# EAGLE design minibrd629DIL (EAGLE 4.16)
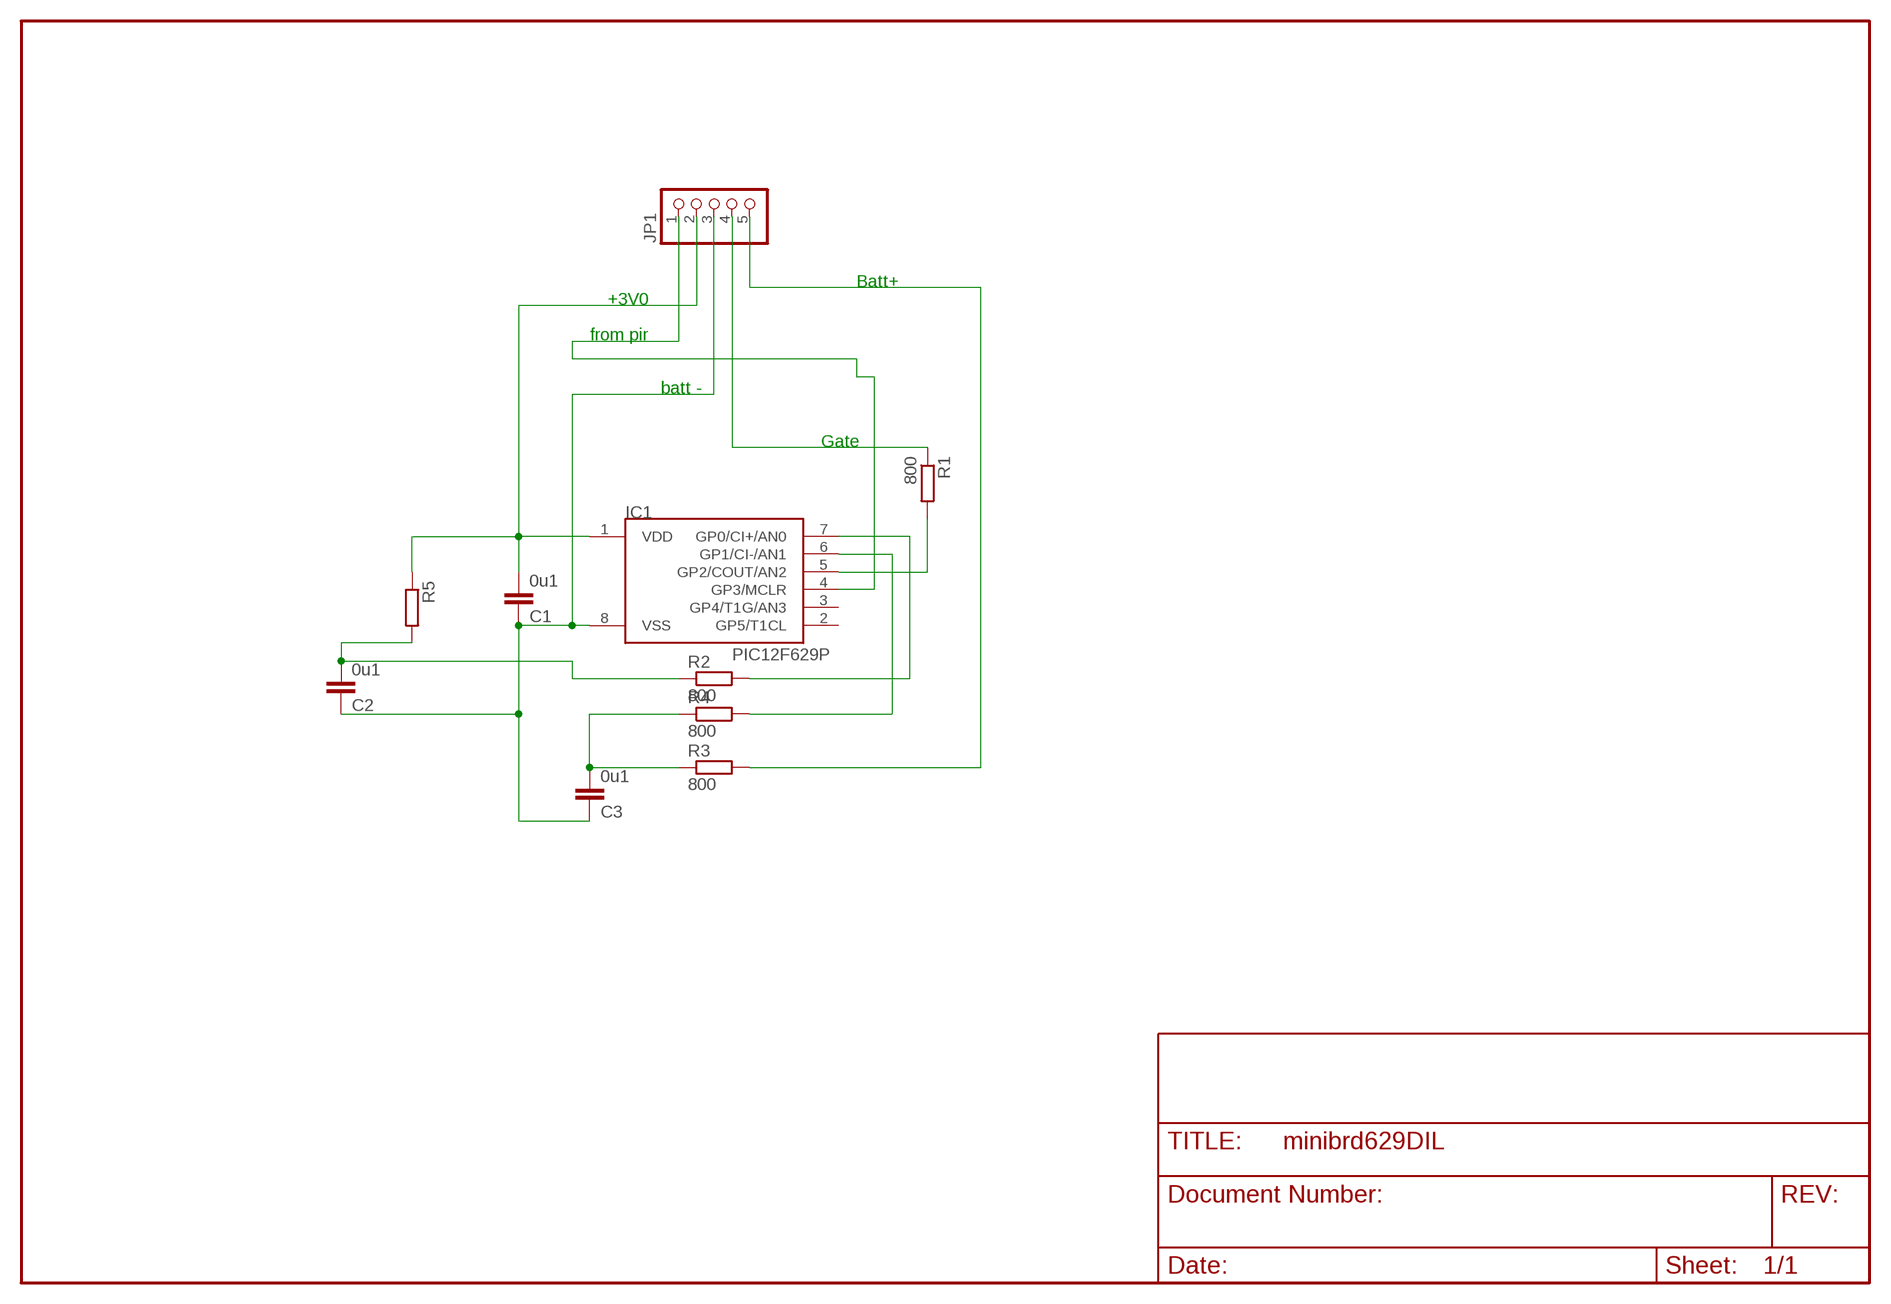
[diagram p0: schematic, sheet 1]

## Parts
C1  0u1  C-EUC1206  [C1206]
C2  0u1  C-EUC1206  [C1206]
C3  0u1  C-EUC1206  [C1206]
IC1  PIC12F629P  [DIL8]
JP1  PINHD-1X5  [1X05]
R1  800  R-EU_R1206  [R1206]
R2  800  R-EU_R1206  [R1206]
R3  800  R-EU_R1206  [R1206]
R4  800  R-EU_R1206  [R1206]
R5  R-EU_0613/5V  [P0613V]

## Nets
GATE: JP1.4 R1.1
N$1: IC1.5(GP2/COUT/AN2) R1.2
N$4: IC1.7(GP0/CI+/AN0) R2.2
N$7: C3.2 R3.1 R4.1
N$8: IC1.6(GP1/CI-/AN1) R4.2
N$9: C2.2 R2.1 R5.2
PIR: IC1.4(GP3/MCLR) JP1.1
V3: C1.2 IC1.1(VDD) JP1.2 R5.1
V+: JP1.5 R3.2
V-: C1.1 C2.1 C3.1 IC1.8(VSS) JP1.3
Unconnected: IC1.2(GP5/T1CL) IC1.3(GP4/T1G/AN3)

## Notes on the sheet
- Batt+
- +3V0
- from pir
- batt -
- Gate

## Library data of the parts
C1-C3 = rcl:C-EU: CAPACITOR, European symbol
IC1 = microchip-3:PIC12F6*: uPC nW 1k Program Flash memory 2x Timer Comparator 10b A/D converter/ 4xIN
JP1 = pinhead:PINHD-1X5: PIN HEADER
R1-R5 = rcl:R-EU_: RESISTOR, European symbol

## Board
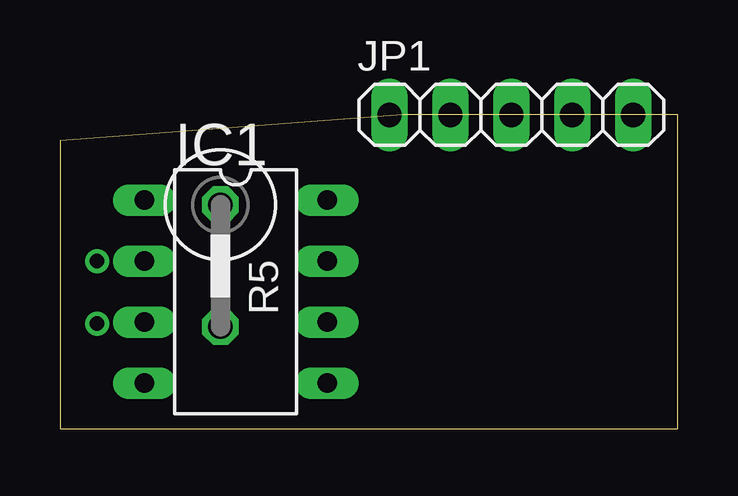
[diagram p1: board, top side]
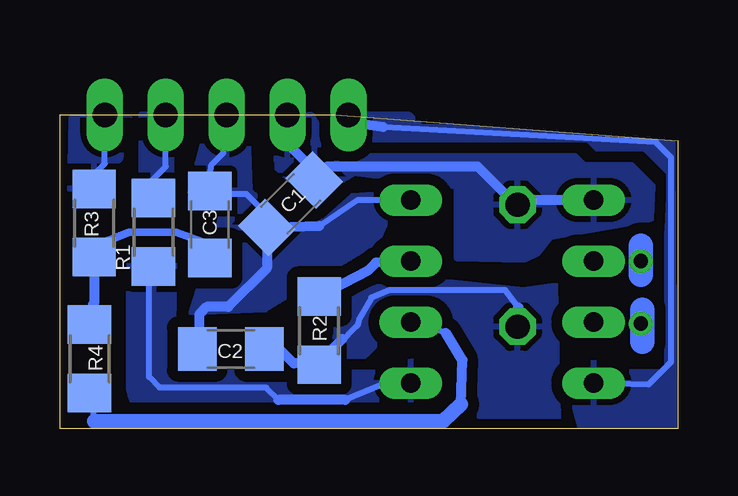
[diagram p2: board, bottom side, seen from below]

Size 25.77 x 13.08 mm. Coordinates in mm from the lower left corner, seen from the top.
Outline: 0,0 25.77,0 25.77,13.07 18,13.07 14.31,13.08 0,11.99 0,0
Copper layers (1*16): Top 0.035mm / dielectric 1.5mm / Bottom 0.035mm
Design rules "default": minimum track width 10mil, minimum drill 24mil, track to track 18mil, track to pad 18mil, pad to pad 8mil, via to via 8mil, smd to smd 8mil, copper to edge 1mil, drill to drill 8mil, minimum pad ring 10mil, minimum via ring 8mil, stop-mask expansion 4mil, vias tented up to drill 0mil, thermal gap 10mil

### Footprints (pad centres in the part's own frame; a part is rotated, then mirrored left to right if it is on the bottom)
C1206 = smd 1.6 x 1.8: 1 -1.4,0; 2 1.4,0
DIL8 = drill 0.813 long: 1 -3.81,-3.81; 2 -1.27,-3.81; 3 1.27,-3.81; 4 3.81,-3.81; 5 3.81,3.81; 6 1.27,3.81; 7 -1.27,3.81; 8 -3.81,3.81
1X05 = drill 1.016 long: 1 -5.08,0; 2 -2.54,0; 3 0,0; 4 2.54,0; 5 5.08,0
R1206 = smd 1.6 x 1.803: 1 -1.422,0; 2 1.422,0
P0613V = drill 1.016 octagon: 1 -2.54,0; 2 2.54,0

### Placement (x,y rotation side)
C1  16.15,9.37 45 bottom
C2  18.64,3.32 0 bottom
C3  19.52,8.5 270 bottom
IC1  7.33,5.71 270 top
JP1  18.82,13.08 0 top
R1  21.87,8.19 270 bottom
R2  14.96,4.09 90 bottom
R3  24.35,8.57 90 bottom
R4  24.54,2.92 270 bottom
R5  6.69,6.79 270 top

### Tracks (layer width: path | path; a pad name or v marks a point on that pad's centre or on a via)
GATE
  Bottom 0.254: JP1.4 21.36,10.92 22.06,10.22 22.06,9.52 21.97,9.61 R1.1
  pour Bottom: 21.11,13.14 22.31,13.14 22.38,13.08 22.38,10.66 22.5,10.54 21.23,10.54 21.11,10.66 21.11,13.01
N$1
  Bottom 0.254: IC1.5 12.34,1.84 13.87,1.2 | R1.2 21.55,6.79 22.06,6.28 22.06,2.15 21.62,1.71 17.17,1.71 16.66,1.2
  Bottom 0.406: 13.87,1.2 16.66,1.2
  pour Bottom (isolate 0.406): 11.46,2.79 10.57,2.85 9.99,2.79 9.99,1.2 22.76,1.2 22.89,1.65 22.89,7.42 22.76,7.55 21.04,7.55 20.98,7.49 21.04,4.38 20.47,3.11 19.71,2.34 12.66,2.34 12.47,2.54 11.71,2.54
N$2  (via drill 0.6)
  other vias: 1.55,4.38
N$3  (via drill 0.6)
  other vias: 1.55,6.98
N$4
  Bottom 0.406: R2.2 12.93,6.59 12.6,6.92 IC1.7
N$5
  Bottom 1.016: 1.49,3.61 1.49,4.95
N$6
  Bottom 1.016: 1.55,6.41 1.55,7.62
N$7
  Bottom 0.254: C3.2 19.39,7.62 | 24.47,7.55 24.45,7.53 R3.1 | R4.1 24.47,5.2 24.41,5.14 24.35,5.2
  Bottom 0.305: 19.39,7.62 20.92,8.19 22.89,8.19 24.47,7.55
  Bottom 0.406: R3.1 24.35,5.2
N$8
  Bottom 0.254: R4.2 24.47,2.15 24.35,0.31 | 9.68,4 IC1.6
  Bottom 0.406: 9.04,1.01 8.98,2.85 9.68,4
  Bottom 0.61: 24.35,0.31 9.8,0.31 9.04,1.01
N$9
  Bottom 0.254: 6.57,4.95 6.65,5.05 7.2,5.77 12.03,5.77 12.79,5.46 13.3,4.57 13.36,4.32 | 13.36,4.32 13.42,4.25 | 13.36,4.32 R2.1 | 15.7,3.16 15.52,2.98 14.76,2.98
  Bottom 0.305: R2.1 13.99,3.74
  Bottom 0.406: 13.99,3.74 14.76,2.98 | C2.2 16.63,3.32 16.03,2.73 15.01,2.73 14.96,2.78 | 14.96,2.78 14.95,2.79 | R2.1 14.96,2.78 | 6.65,5.05 6.66,5.05 6.69,5.01 R5.2
  pour Bottom (isolate 0.406, rank 2): 4.98,0.38 5.11,5.96 6.44,5.77 12.53,6.41 12.66,6.28 12.85,6.28 14.25,4.88 14.25,3.87 14.63,3.49 14.63,3.3 14.06,2.73 13.36,2.73 12.66,3.42 12.66,5.08 12.47,5.39 8.15,0.38
PIR
  Bottom 0.254: IC1.4 1.23,1.84 0.28,2.79 0.28,11.3 0.91,11.93 12.28,12.57 | 13.74,12.76 JP1.1
  Bottom 0.406: 12.28,12.57 13.74,12.76
  pour Bottom (rank 2): 1.99,2.73 3.77,2.73 4.34,2.15 4.34,1.01 4.09,0.12 0.15,0.12 0.22,11.87 0.34,12 3.77,12 4.34,12.57 10.69,12.57 11.2,13.08 13.74,13.08 14.31,12.5 14.31,12.38 13.23,11.3 12.22,11.3 11.52,12 7.52,12 7.14,11.62 2.06,11.62 0.47,10.41 0.47,2.47 0.72,2.34 1.99,2.34 2.18,2.54
V3
  Bottom 0.406: 6.76,9.33 6.82,9.39 6.69,9.52 IC1.1 | 6.76,9.33 R5.1 | 6.76,9.33 8.34,10.92 14.57,10.92 | C1.2 15.12,10.36 14.57,10.92 | 14.57,10.92 14.63,10.92 15.2,10.35 15.2,10.79 16.47,12.06 16.47,12.95 16.35,13.08 JP1.2
  pour Bottom: 5.3,8 1.36,8.69 1.1,8.76 1.04,10.09 1.93,10.98 3.9,10.98 4.28,11.36 12.85,11.36 13.36,11.23 14.38,11.42 15.27,13.08 16.79,12.89 16.73,10.85 15.58,9.77 15.14,9.71 13.49,10.66 9.23,10.09 9.23,7.11 6.38,7.04 5.87,7.3
V+
  Bottom 0.254: R3.2 24.37,10.37 24.47,10.47 23.9,11.04 JP1.5
  pour Bottom: 22.82,12.89 25.3,12.95 25.36,9.96 23.27,11.23
V-
  Bottom 0.254: C3.1 19.46,10.98 18.95,11.49 18.95,13.01 18.89,13.08 JP1.3 | C3.1 18.76,9.59 | IC1.8 13.36,9.52 14.95,8.44 | 16.79,8.38 C1.1 17.14,8.92 18,9.77 19.08,9.77 19.14,9.71 19.33,9.9 C3.1
  Bottom 0.406: 14.95,8.44 16.79,8.38 | C1.1 17.14,6.69 18.76,5.08 19.65,5.08 19.96,4.76 19.96,3.68 20.04,3.6 C2.1
  pour Bottom: 11.9,9.84 11.77,9.52 12.53,7.81 17.23,4.95 20.28,4.82 18.82,9.52 20.03,9.52 20.35,9.84 19.71,12.19 18,12.12 17.93,11.68 17.87,9.9 17.04,9.27 15.84,8.19 14.69,8.69 13.55,9.71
